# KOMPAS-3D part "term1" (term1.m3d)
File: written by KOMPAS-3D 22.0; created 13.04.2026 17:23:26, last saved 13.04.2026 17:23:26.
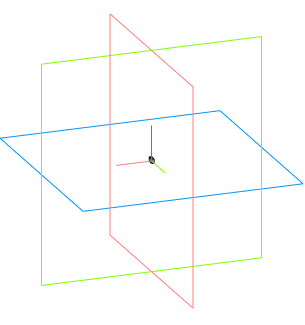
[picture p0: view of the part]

Document properties: Автор: Andrey; Полное имя файла: C:\Users\User1\Documents\term1.m3d

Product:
- Part/product: term1

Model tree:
1. Операция без истории:1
